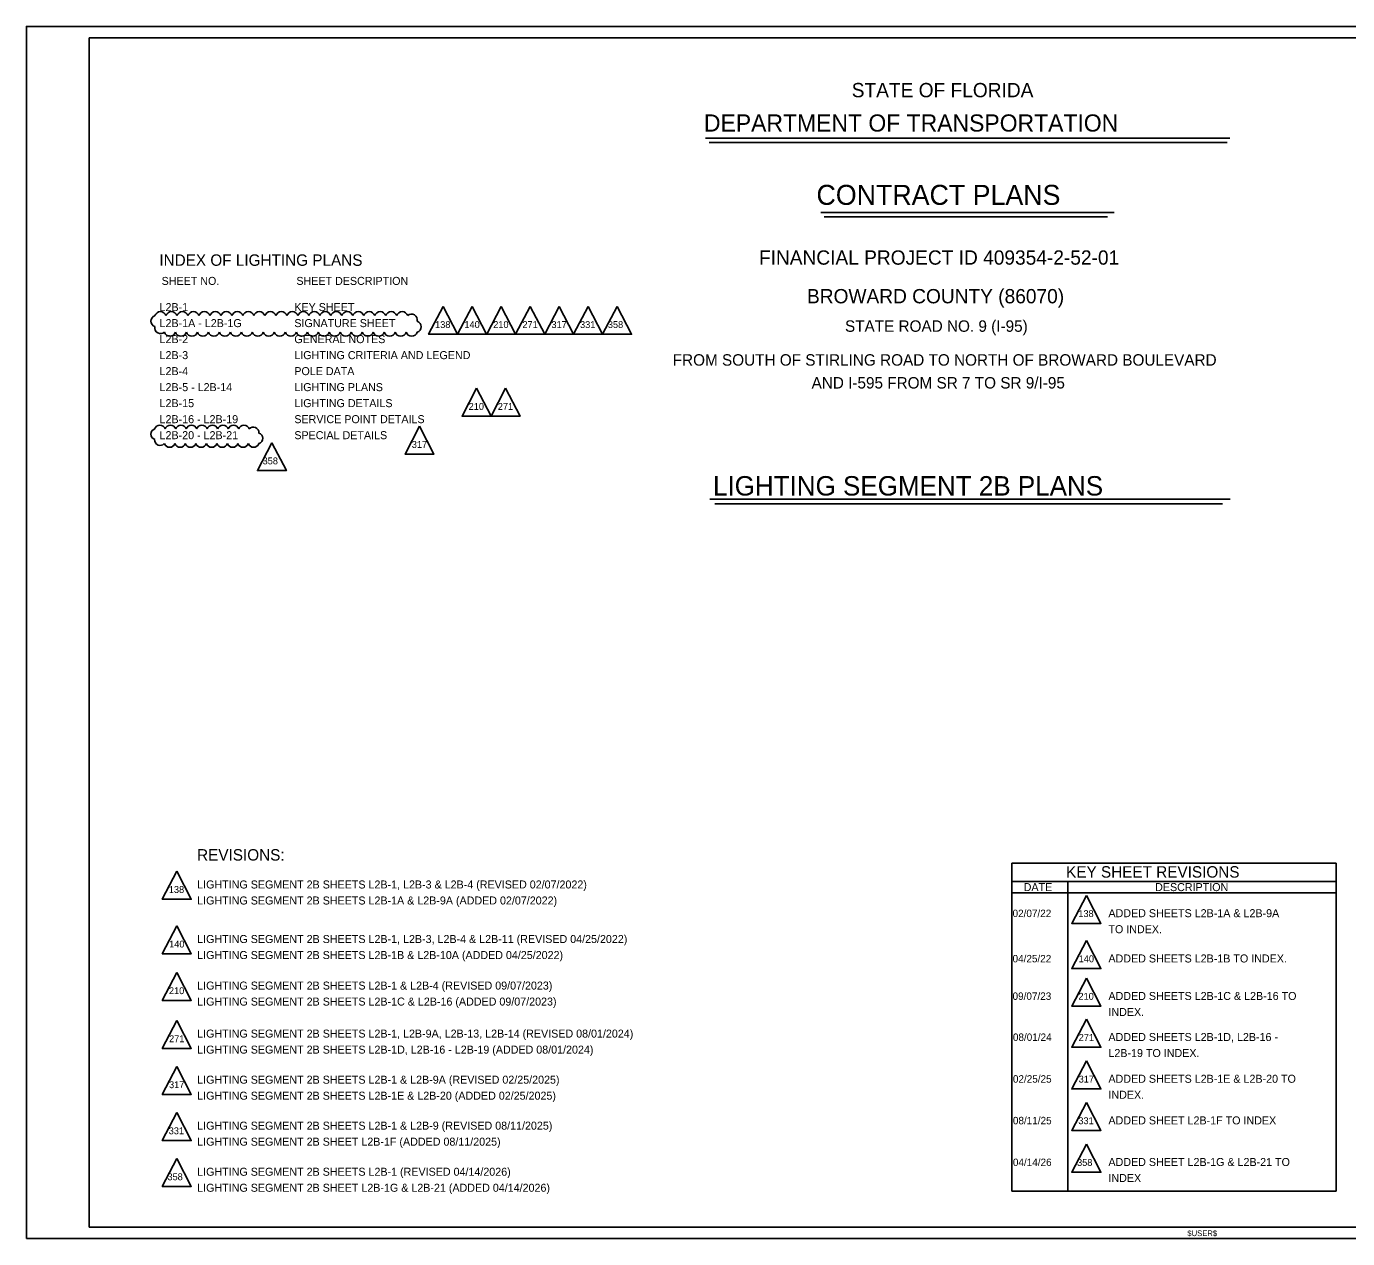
# Model space of a CAD drawing. Extents: x -820.2 to -798.1, y -2199.1 to -2188.5.
# Drawn here: x -820.23 to -808.68, y -2199.12 to -2188.52 of the extents above; entities that cross this region are included whole.
import ezdxf

# ---------------------------------------------------------------- set-up
doc = ezdxf.new("R2010")
doc.units = 0
for name, color, linetype in [('AdhocPoint_dp', 7, 'Continuous'), ('Cloud_dp', 7, 'Continuous'), ('PlotBorder_dp', 7, 'Continuous'), ('SheetBorder_dp', 7, 'Continuous'), ('SumBoxLines_dp', 7, 'Continuous'), ('TextLabel', 7, 'Continuous'), ('TextMinor', 7, 'Continuous'), ('TextNotes', 7, 'Continuous'), ('TextTitle', 7, 'Continuous')]:
    doc.layers.add(name, color=color, linetype=linetype)

msp = doc.modelspace()

# ---------------------------------------------------------------- linework, layer by layer
at = {"layer": 'AdhocPoint_dp'}
msp.add_line((-820.227, -2199.124), (-820.227, -2199.124), dxfattribs=at)
at = {"layer": 'Cloud_dp'}
for points in [[(-816.585, -2190.972), (-816.711, -2191.216), (-816.458, -2191.216)], [(-816.331, -2190.972), (-816.458, -2191.216), (-816.204, -2191.216)], [(-816.077, -2190.972), (-816.203, -2191.216), (-815.95, -2191.216)], [(-815.823, -2190.972), (-815.95, -2191.216), (-815.696, -2191.216)], [(-815.57, -2190.972), (-815.696, -2191.216), (-815.443, -2191.216)], [(-815.316, -2190.972), (-815.443, -2191.216), (-815.19, -2191.216)], [(-815.063, -2190.972), (-815.19, -2191.216), (-814.936, -2191.216)], [(-816.292, -2191.688), (-816.419, -2191.932), (-816.165, -2191.932)], [(-816.038, -2191.688), (-816.165, -2191.932), (-815.912, -2191.932)], [(-816.79, -2192.02), (-816.917, -2192.264), (-816.664, -2192.264)], [(-818.081, -2192.164), (-818.208, -2192.408), (-817.954, -2192.408)], [(-818.912, -2195.912), (-819.039, -2196.156), (-818.786, -2196.156)], [(-810.961, -2196.123), (-811.088, -2196.367), (-810.834, -2196.367)], [(-818.912, -2196.389), (-819.039, -2196.633), (-818.786, -2196.633)], [(-810.961, -2196.518), (-811.088, -2196.762), (-810.834, -2196.762)], [(-818.912, -2196.797), (-819.039, -2197.041), (-818.786, -2197.041)], [(-810.961, -2196.846), (-811.088, -2197.09), (-810.834, -2197.09)], [(-818.912, -2197.217), (-819.039, -2197.461), (-818.786, -2197.461)], [(-810.961, -2197.205), (-811.088, -2197.45), (-810.834, -2197.45)], [(-818.912, -2197.619), (-819.039, -2197.863), (-818.786, -2197.863)], [(-810.961, -2197.57), (-811.088, -2197.814), (-810.834, -2197.814)], [(-810.961, -2197.934), (-811.088, -2198.178), (-810.834, -2198.178)], [(-818.912, -2198.022), (-819.039, -2198.266), (-818.786, -2198.266)], [(-810.961, -2198.299), (-811.088, -2198.543), (-810.834, -2198.543)], [(-818.912, -2198.424), (-819.039, -2198.668), (-818.786, -2198.668)]]:
    msp.add_lwpolyline(points, close=True, dxfattribs=at)
for centre, radius, start, end in [((-819.088, -2191.101), 0.0504, 107.5, 252.5), ((-819.055, -2191.068), 0.0504, 17.5, 162.5), ((-818.959, -2191.068), 0.0504, 17.5, 162.5), ((-818.863, -2191.068), 0.0504, 17.5, 162.5), ((-818.767, -2191.068), 0.0504, 17.5, 162.5), ((-818.671, -2191.068), 0.0504, 17.5, 162.5), ((-818.575, -2191.068), 0.0504, 17.5, 162.5), ((-818.479, -2191.068), 0.0504, 17.5, 162.5), ((-818.383, -2191.068), 0.0504, 17.5, 162.5), ((-818.287, -2191.068), 0.0504, 17.5, 162.5), ((-818.191, -2191.068), 0.0504, 17.5, 162.5), ((-818.094, -2191.068), 0.0504, 17.5, 162.5), ((-817.998, -2191.068), 0.0504, 17.5, 162.5), ((-817.902, -2191.068), 0.0504, 17.5, 162.5), ((-817.806, -2191.068), 0.0504, 17.5, 162.5), ((-817.71, -2191.068), 0.0504, 17.5, 162.5), ((-817.614, -2191.068), 0.0504, 17.5, 162.5), ((-817.518, -2191.068), 0.0504, 17.5, 162.5), ((-817.422, -2191.068), 0.0504, 17.5, 162.5), ((-817.326, -2191.068), 0.0504, 17.5, 162.5), ((-817.23, -2191.068), 0.0504, 17.5, 162.5), ((-817.134, -2191.068), 0.0504, 17.5, 162.5), ((-817.038, -2191.068), 0.0504, 17.5, 162.5), ((-816.942, -2191.068), 0.0504, 17.5, 162.5), ((-816.86, -2191.09), 0.0503, 347.2695, 132.2695), ((-819.054, -2191.16), 0.0503, 167.2695, 312.2695), ((-816.826, -2191.15), 0.0504, 287.5, 72.5), ((-818.972, -2191.182), 0.0504, 197.5, 342.5), ((-818.876, -2191.182), 0.0504, 197.5, 342.5), ((-818.78, -2191.182), 0.0504, 197.5, 342.5), ((-818.684, -2191.182), 0.0504, 197.5, 342.5), ((-818.588, -2191.182), 0.0504, 197.5, 342.5), ((-818.492, -2191.182), 0.0504, 197.5, 342.5), ((-818.396, -2191.182), 0.0504, 197.5, 342.5), ((-818.3, -2191.182), 0.0504, 197.5, 342.5), ((-818.204, -2191.182), 0.0504, 197.5, 342.5), ((-818.108, -2191.182), 0.0504, 197.5, 342.5), ((-818.012, -2191.182), 0.0504, 197.5, 342.5), ((-817.915, -2191.182), 0.0504, 197.5, 342.5), ((-817.819, -2191.182), 0.0504, 197.5, 342.5), ((-817.723, -2191.182), 0.0504, 197.5, 342.5), ((-817.627, -2191.182), 0.0504, 197.5, 342.5), ((-817.531, -2191.182), 0.0504, 197.5, 342.5), ((-817.435, -2191.182), 0.0504, 197.5, 342.5), ((-817.339, -2191.182), 0.0504, 197.5, 342.5), ((-817.243, -2191.182), 0.0504, 197.5, 342.5), ((-817.147, -2191.182), 0.0504, 197.5, 342.5), ((-817.051, -2191.182), 0.0504, 197.5, 342.5), ((-816.955, -2191.182), 0.0504, 197.5, 342.5), ((-816.859, -2191.182), 0.0504, 197.5, 342.5), ((-819.091, -2192.089), 0.0481, 107.5, 252.5), ((-819.06, -2192.058), 0.0481, 17.5, 162.5), ((-818.968, -2192.058), 0.0481, 17.5, 162.5), ((-818.876, -2192.058), 0.0481, 17.5, 162.5), ((-818.784, -2192.058), 0.0481, 17.5, 162.5), ((-818.693, -2192.058), 0.0481, 17.5, 162.5), ((-818.601, -2192.058), 0.0481, 17.5, 162.5), ((-818.509, -2192.058), 0.0481, 17.5, 162.5), ((-818.417, -2192.058), 0.0481, 17.5, 162.5), ((-818.325, -2192.058), 0.0481, 17.5, 162.5), ((-818.243, -2192.075), 0.0481, 354.6822, 139.6822), ((-818.209, -2192.125), 0.0481, 287.5, 72.5), ((-819.058, -2192.14), 0.0481, 174.6822, 319.6822), ((-818.975, -2192.156), 0.0481, 197.5, 342.5), ((-818.883, -2192.156), 0.0481, 197.5, 342.5), ((-818.792, -2192.156), 0.0481, 197.5, 342.5), ((-818.7, -2192.156), 0.0481, 197.5, 342.5), ((-818.608, -2192.156), 0.0481, 197.5, 342.5), ((-818.516, -2192.156), 0.0481, 197.5, 342.5), ((-818.424, -2192.156), 0.0481, 197.5, 342.5), ((-818.333, -2192.156), 0.0481, 197.5, 342.5), ((-818.241, -2192.156), 0.0481, 197.5, 342.5)]:
    msp.add_arc(centre, radius, start, end, dxfattribs=at)
at = {"layer": 'PlotBorder_dp'}
msp.add_lwpolyline([(-820.227, -2199.124), (-803.727, -2199.124), (-803.727, -2188.524), (-820.227, -2188.524)], close=True, dxfattribs=at)
at = {"layer": 'SheetBorder_dp'}
for p, q in [((-819.677, -2188.624), (-819.677, -2199.024)), ((-819.677, -2188.624), (-804.277, -2188.624)), ((-819.677, -2199.024), (-804.277, -2199.024))]:
    msp.add_line(p, q, dxfattribs=at)
at = {"layer": 'SumBoxLines_dp'}
for p, q in [((-811.612, -2195.84), (-811.612, -2198.708)), ((-811.612, -2195.84), (-808.777, -2195.84)), ((-808.777, -2195.84), (-808.777, -2198.708)), ((-811.612, -2196), (-808.777, -2196)), ((-811.122, -2196), (-811.122, -2198.708)), ((-811.612, -2196.1), (-808.777, -2196.1)), ((-811.612, -2198.708), (-808.777, -2198.708))]:
    msp.add_line(p, q, dxfattribs=at)
at = {"layer": 'TextTitle'}
for p, q in [((-814.289, -2189.5), (-809.707, -2189.5)), ((-814.257, -2189.538), (-809.729, -2189.538)), ((-813.281, -2190.15), (-810.719, -2190.15)), ((-813.253, -2190.188), (-810.777, -2190.188)), ((-814.252, -2192.659), (-809.704, -2192.659)), ((-814.209, -2192.697), (-809.772, -2192.697))]:
    msp.add_line(p, q, dxfattribs=at)

# ---------------------------------------------------------------- texts
at = {"layer": 'Cloud_dp'}
for s, p in [('138', (-816.654, -2191.161)), ('140', (-816.398, -2191.161)), ('210', (-816.146, -2191.161)), ('271', (-815.891, -2191.161)), ('317', (-815.637, -2191.161)), ('331', (-815.387, -2191.161)), ('358', (-815.144, -2191.161)), ('210', (-816.361, -2191.877)), ('271', (-816.106, -2191.877)), ('317', (-816.858, -2192.209)), ('358', (-818.162, -2192.353)), ('138', (-818.982, -2196.101)), ('138', (-811.031, -2196.312)), ('140', (-818.979, -2196.578)), ('140', (-811.028, -2196.707)), ('210', (-818.981, -2196.986)), ('210', (-811.03, -2197.035)), ('271', (-818.98, -2197.406)), ('271', (-811.028, -2197.395)), ('317', (-818.98, -2197.808)), ('317', (-811.028, -2197.759)), ('331', (-811.031, -2198.123)), ('331', (-818.983, -2198.211)), ('358', (-811.042, -2198.488)), ('358', (-818.994, -2198.613))]:
    msp.add_text(s, height=0.06, rotation=0, dxfattribs=at).set_placement(p)
at = {"layer": 'TextLabel'}
for s, height, p in [('FINANCIAL PROJECT ID 409354-2-52-01', 0.125, (-813.823, -2190.607)), ('INDEX OF LIGHTING PLANS', 0.1, (-819.065, -2190.617)), ('BROWARD COUNTY (86070)', 0.125, (-813.403, -2190.945)), ('L2B-1', 0.07, (-819.063, -2191.013)), ('KEY SHEET', 0.07, (-817.885, -2191.013)), ('L2B-1A - L2B-1G', 0.07, (-819.063, -2191.153)), ('SIGNATURE SHEET', 0.07, (-817.885, -2191.153)), ('STATE ROAD NO. 9 (I-95)', 0.1, (-813.071, -2191.194)), ('L2B-2', 0.07, (-819.063, -2191.293)), ('GENERAL NOTES', 0.07, (-817.885, -2191.293)), ('L2B-3', 0.07, (-819.063, -2191.433)), ('LIGHTING CRITERIA AND LEGEND', 0.07, (-817.885, -2191.433)), ('FROM SOUTH OF STIRLING ROAD TO NORTH OF BROWARD BOULEVARD', 0.1, (-814.577, -2191.49)), ('L2B-4', 0.07, (-819.063, -2191.573)), ('POLE DATA', 0.07, (-817.885, -2191.573)), ('L2B-5 - L2B-14', 0.07, (-819.063, -2191.713)), ('LIGHTING PLANS', 0.07, (-817.885, -2191.713)), ('AND I-595 FROM SR 7 TO SR 9/I-95', 0.1, (-813.363, -2191.69)), ('L2B-15', 0.07, (-819.063, -2191.853)), ('LIGHTING DETAILS', 0.07, (-817.885, -2191.853)), ('L2B-16 - L2B-19', 0.07, (-819.063, -2191.993)), ('SERVICE POINT DETAILS', 0.07, (-817.885, -2191.993)), ('L2B-20 - L2B-21', 0.07, (-819.063, -2192.133)), ('SPECIAL DETAILS', 0.07, (-817.885, -2192.133)), ('REVISIONS:', 0.1, (-818.735, -2195.818)), ('KEY SHEET REVISIONS', 0.1, (-811.138, -2195.967))]:
    msp.add_text(s, height=height, dxfattribs=at).set_placement(p)
at = {"layer": 'TextMinor'}
for s, height, p in [('02/07/22', 0.065, (-811.606, -2196.312)), ('ADDED SHEETS L2B-1A & L2B-9A ', 0.07, (-810.768, -2196.313)), ('TO INDEX.', 0.07, (-810.768, -2196.453)), ('04/25/22', 0.065, (-811.606, -2196.708)), ('ADDED SHEETS L2B-1B TO INDEX.', 0.07, (-810.768, -2196.709)), ('09/07/23', 0.065, (-811.606, -2197.036)), ('ADDED SHEETS L2B-1C & L2B-16 TO ', 0.07, (-810.768, -2197.037)), ('INDEX.', 0.07, (-810.768, -2197.177)), ('08/01/24', 0.065, (-811.603, -2197.395)), ('ADDED SHEETS L2B-1D, L2B-16 - ', 0.07, (-810.768, -2197.396)), ('L2B-19 TO INDEX.', 0.07, (-810.768, -2197.536)), ('02/25/25', 0.065, (-811.603, -2197.76)), ('ADDED SHEETS L2B-1E & L2B-20 TO ', 0.07, (-810.768, -2197.761)), ('INDEX.', 0.07, (-810.768, -2197.901)), ('08/11/25', 0.065, (-811.603, -2198.124)), ('ADDED SHEET L2B-1F TO INDEX', 0.07, (-810.768, -2198.125)), ('04/14/26', 0.065, (-811.603, -2198.489)), ('ADDED SHEET L2B-1G & L2B-21 TO ', 0.07, (-810.768, -2198.489)), ('INDEX', 0.07, (-810.768, -2198.629)), ('$USER$', 0.05, (-810.078, -2199.102))]:
    msp.add_text(s, height=height, dxfattribs=at).set_placement(p)
at = {"layer": 'TextNotes'}
for s, height, p in [('SHEET NO.', 0.07, (-819.045, -2190.784)), ('SHEET DESCRIPTION', 0.07, (-817.867, -2190.784)), ('LIGHTING SEGMENT 2B SHEETS L2B-1, L2B-3 & L2B-4 (REVISED 02/07/2022)', 0.06998, (-818.734, -2196.062)), ('DATE', 0.07, (-811.509, -2196.085)), ('DESCRIPTION', 0.07, (-810.36, -2196.085)), ('LIGHTING SEGMENT 2B SHEETS L2B-1A & L2B-9A (ADDED 02/07/2022)', 0.06998, (-818.734, -2196.202)), ('LIGHTING SEGMENT 2B SHEETS L2B-1, L2B-3, L2B-4 & L2B-11 (REVISED 04/25/2022)', 0.06998, (-818.734, -2196.539)), ('LIGHTING SEGMENT 2B SHEETS L2B-1B & L2B-10A (ADDED 04/25/2022)', 0.06998, (-818.734, -2196.679)), ('LIGHTING SEGMENT 2B SHEETS L2B-1 & L2B-4 (REVISED 09/07/2023)', 0.06998, (-818.734, -2196.946)), ('LIGHTING SEGMENT 2B SHEETS L2B-1C & L2B-16 (ADDED 09/07/2023)', 0.06998, (-818.734, -2197.086)), ('LIGHTING SEGMENT 2B SHEETS L2B-1, L2B-9A, L2B-13, L2B-14 (REVISED 08/01/2024)', 0.06998, (-818.734, -2197.366)), ('LIGHTING SEGMENT 2B SHEETS L2B-1D, L2B-16 - L2B-19 (ADDED 08/01/2024)', 0.06998, (-818.734, -2197.506)), ('LIGHTING SEGMENT 2B SHEETS L2B-1 & L2B-9A (REVISED 02/25/2025)', 0.06998, (-818.734, -2197.769)), ('LIGHTING SEGMENT 2B SHEETS L2B-1E & L2B-20 (ADDED 02/25/2025)', 0.06998, (-818.734, -2197.909)), ('LIGHTING SEGMENT 2B SHEETS L2B-1 & L2B-9 (REVISED 08/11/2025)', 0.06998, (-818.734, -2198.171)), ('LIGHTING SEGMENT 2B SHEET L2B-1F (ADDED 08/11/2025)', 0.06998, (-818.734, -2198.311)), ('LIGHTING SEGMENT 2B SHEETS L2B-1 (REVISED 04/14/2026)', 0.06998, (-818.734, -2198.574)), ('LIGHTING SEGMENT 2B SHEET L2B-1G & L2B-21 (ADDED 04/14/2026)', 0.06998, (-818.734, -2198.714))]:
    msp.add_text(s, height=height, dxfattribs=at).set_placement(p)
at = {"layer": 'TextTitle'}
for s, height, p in [('STATE OF FLORIDA', 0.125, (-813.012, -2189.143)), ('DEPARTMENT OF TRANSPORTATION', 0.15, (-814.304, -2189.443)), ('CONTRACT PLANS', 0.175, (-813.32, -2190.084)), ('LIGHTING SEGMENT 2B PLANS', 0.17, (-814.225, -2192.626))]:
    msp.add_text(s, height=height, dxfattribs=at).set_placement(p)

doc.saveas('drawing.dxf')
